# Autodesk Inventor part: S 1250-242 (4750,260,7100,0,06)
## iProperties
Category: PARTsolutions
Created: 2011-08
Part Number: S 1250-242 (4750,260,7100,0,06)
Catalog Web Link: www.cadenas.de
Description: 1250 Führungskanal - Führungskanal
Document SubType Name: Modeling
Designer: PARTsolutions
Density: 1 g/cm^3
NB: S 1250-242 (4750,260,7100,0,06)
NN: 1250 Führungskanal
NT: Führungskanal
NBSYN: $TYP.-$BI. ($LK.,$KR.,$LS.,$LV.,$ESP.$STEGV.)
LINA: S 1250-242 (4750,260,7100,0,06)
TYP: S 1250
BI: 242
BK: 291
LK: 4750
KR: 260
LS: 7100
LV: 0
STEGV: 6
LF: 3737.500
ESP: 0
PSTOL: 0.010
T: 125.000
LS2: 3550.000
DR: 83.186
LB: 1191.814
EASS: 0.000
VAR: 1.000
LKA: 4875.000
MOD1: 1.000
RX2: 520.000
HI: 69.000
HG: 94
TYP1: S1250
BIMIN: 101.000
BIMAX: 751.000
KRV: 145,200,220,260,300,340,380,420,460,500,540,600,700
LSMAX: 150000.000
BKMIN: 150.000
BKMAX: 800.000
BST: 267.000
BST1: 267.000
PIN: 18.800
KT: DUMMY
SUPPLIER: Kabelschlepp
ARTICLENO: S 1250-242 (4750,260,7100,0,06)
BOMINFO: S 1250-242 (4750,260,7100,0,06)
CREATOR: CADENAS GmbH
PSOL_IDENT_0: {\\10.0.0.251\ps_data\23d-libs\kabelschlepp\4_eketten_st\parts\1250_kabelkanal.prj},237 {VTYP=3D},{N
PSOL_IDENT_1: B=S 1250-242 (4750,260,7100,0,06)},{LINA=S 1250-242 (4750,260,7100,0,06)},{NN=1250 Führungskanal},{D
PSOL_IDENT_2: ATE=31.05.2007 07:52:20},{GEOMDATE=19.03.2007 11:05:00},{VERSION=},{LINEID=10},{LINESUBID=-1},{WBVAR
PSOL_IDENT_3: =BI,KR,LS,LV,STEGV,ESP}  {NB=S 1250-242 (4750,260,7100,0,06)},{LINA=S 1250-242 (4750,260,7100,0,06)}
PSOL_IDENT_4: ,{KT=DUMMY},{TYP=S 1250},{BI=242},{BK=291},{LK=4750},{KR=260},{LS=7100},{LV=0},{STEGV=6},{LF=3737.5}
PSOL_IDENT_5: ,{ESP=0},{PSTOL=0.010},{T=125.000},{LS2=3550},{DR=83.18591},{LB=1191.81409},{EASS=0},{VAR=1},{LKA=48
PSOL_IDENT_6: 75},{MOD1=1},{RX2=520},{NB1=},{HI=69},{HG=94},{TYP1=S1250},{BIMIN=101},{BIMAX=751},{KRV=145,200,220,
PSOL_IDENT_7: 260,300,340,380,420,460,500,540,600,700},{LSMAX=150000.000},{SV=-1000000015047466200000000000000.00}
PSOL_IDENT_8: ,{SV1=},{BKMIN=150},{BKMAX=800},{BST=267},{BST1=267},{PIN=18.8}
Title: S 1250-242 (4750,260,7100,0,06)
Author: Cadenas PARTsolutions
Comments: Führungskanal
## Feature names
1. Extrusion1
